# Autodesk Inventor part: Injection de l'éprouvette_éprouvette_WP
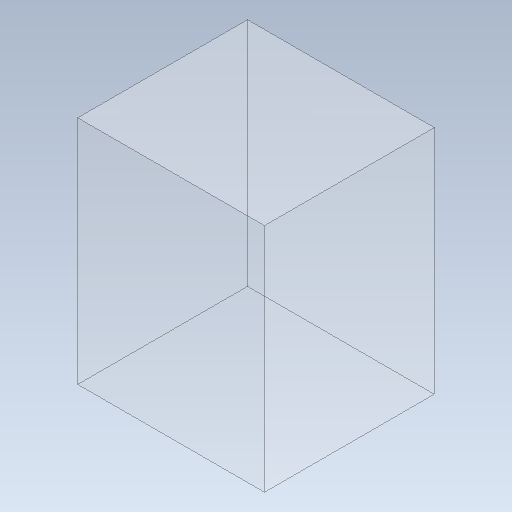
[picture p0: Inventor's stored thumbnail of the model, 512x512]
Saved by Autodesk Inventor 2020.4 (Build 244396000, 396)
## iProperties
Created: 2021-10
Part Number: Injection de l'éprouvette_éprouvette_WP
Material: Générique
Document SubType Name: Modeling
Designer: mel
Density: 1 g/cm^3
Appearance: Par défaut
Author: mel
d0: -25,000 mm
d1: 27,500 mm
d2: 27,500 mm
d3: 34,000 mm
d4: 34,000 mm
d5: 50,000 mm
d6: 0,00 deg
Xmin: -27,500 mm
Ymin: -34,000 mm
Zmin: -25,000 mm
Xmax: 27,500 mm
Ymax: 34,000 mm
Zmax: 25,000 mm
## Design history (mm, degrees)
sketch "Esquisse1"
  geometry: L1 (-27.5, 34)-(27.5, 34); L2 (27.5, 34)-(27.5, -34); L3 (27.5, -34)-(-27.5, -34); L4 (-27.5, -34)-(-27.5, 34); 1 further point
  constraints: 8 end point, 2 parallel, 1 horizontal, 1 perpendicular, 1 other
  dimensions: "d1" = 27.5 distance from line of L4 point (0, 0) (= -Xmin); "d2" = 27.5 distance from line of L2 point (0, 0) (= Xmax); "d3" = 34 distance from line of L3 point (0, 0) (= -Ymin); "d4" = 34 distance from line of L1 point (0, 0) (= Ymax)
extrude "Extrusion1" join sketch "Esquisse1" distance "d5" = 50 (= Zmax - Zmin); taper "d6" = 0 deg
node "Solide1"
other parameters: "Xmin" = -27.5 [user parameter; used in 1 equation term], "Ymin" = -34 [user parameter; used in 1 equation term], "Zmin" = -25 [user parameter; used in 1 equation term], "Xmax" = 27.5 [user parameter; used in 1 equation term], "Ymax" = 34 [user parameter; used in 1 equation term], "Zmax" = 25 [user parameter; used in 1 equation term], "d0" = -25
